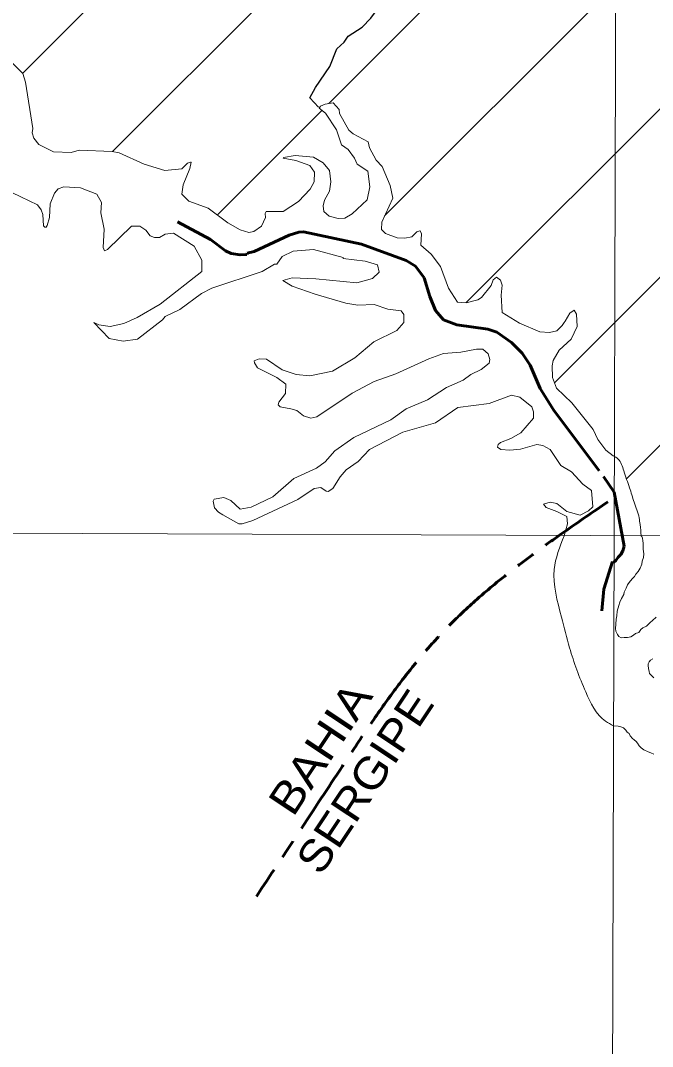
# Model space of a CAD drawing. Extents: x 553962 to 842807, y 8883888 to 9032388.
# Drawn here: x 602280 to 610250, y 8943266 to 8956198 of the extents above; entities that cross this region are included whole.
import ezdxf
from ezdxf.enums import TextEntityAlignment as Align

# ---------------------------------------------------------------- set-up
doc = ezdxf.new("R2010")
doc.units = 0
doc.header["$LTSCALE"] = 160
doc.linetypes.add('LONG_DASH_SHORT_DASH', pattern=[9.9, 6, -1.2, 1.5, -1.2])
for name, color, linetype, lineweight in [('2', 7, 'Continuous', 13), ('21', 7, 'Continuous', 25), ('30', 7, 'Continuous', 13), ('34', 7, 'LONG_DASH_SHORT_DASH', 60)]:
    doc.layers.add(name, color=color, linetype=linetype, lineweight=lineweight)

msp = doc.modelspace()

# ---------------------------------------------------------------- linework, layer by layer
at = {"layer": '2'}
msp.add_line((565315.3, 8949866.8), (791497.7, 8949052.2), dxfattribs=at)
msp.add_lwpolyline([(609971.9, 9023551.8), (609764.7, 8949706.7), (609702.8, 8928779.6)], dxfattribs=at)
at = {"layer": '21'}
msp.add_lwpolyline([(606039.3, 8955103.8), (605929.6, 8955224.5), (605999.4, 8955353.7), (606180, 8955619.3), (606269.2, 8955840.2), (606360.2, 8955926.9), (606411.5, 8955999.5), (606589.9, 8956112.1), (606699.8, 8956226.1), (606821.6, 8956390.6), (606950.7, 8956641.4)], dxfattribs=at)
at = {"layer": '21', "lineweight": 13}
for points in [[(604895.8, 8953649.4), (604648, 8953830.8), (604402.7, 8953921.2), (604313.5, 8954010.1), (604331.8, 8954124.8), (604416, 8954332.4), (604432.7, 8954411.5), (604424.9, 8954413.6), (604386.7, 8954398.7), (604315.2, 8954330), (604098.3, 8954307.6), (603837.5, 8954388.2), (603522.6, 8954529.5), (603434.3, 8954545.5), (603019.3, 8954562.1), (602920.8, 8954535.9), (602695.5, 8954541), (602512.3, 8954636.9), (602447.2, 8954715.8), (602427.7, 8954781.3), (602434.1, 8954838.6), (602343.7, 8955420.5), (602307.6, 8955528.7), (602034.6, 8955801.4)], [(609755.4, 8950712.2), (609661.1, 8950783.5), (609561, 8950917.9), (609502.2, 8951042.1), (609232.8, 8951376.9), (609037.8, 8951563.3), (608987.2, 8951699.7), (608983.5, 8951846.5), (608997.5, 8951911.8), (609071.5, 8952043.1), (609222.8, 8952181.3), (609297.8, 8952340.2), (609292, 8952494.6), (609262.3, 8952545.1), (609208.4, 8952508.9), (609150.1, 8952407.8), (609137, 8952393.4), (609112.2, 8952354.9), (609043.5, 8952286.2), (608950.9, 8952265), (608829.5, 8952275.2), (608570.6, 8952384.4), (608354.7, 8952517.4), (608341.8, 8952734.8), (608352.3, 8952862.7), (608331.7, 8952926.3), (608281.3, 8952961.5), (608241.6, 8952927.5), (608214.1, 8952858.4), (608092.3, 8952708.4), (608046.9, 8952676.2), (607900.7, 8952638.1), (607791.6, 8952649), (607678.7, 8952823.7), (607576.2, 8953096.8), (607460.3, 8953252.1), (607330.5, 8953367), (607335.3, 8953510.5), (607319.8, 8953546.9), (607315.4, 8953548.9), (607278.7, 8953534.6), (607216.5, 8953473.1), (607127, 8953454.3), (607030.5, 8953457.3), (606882.1, 8953514.2), (606832.1, 8953564.1), (606835, 8953655.9), (606976.1, 8953957.7), (606939.6, 8954118.5), (606839.8, 8954356.2), (606764, 8954436.8), (606681.6, 8954591.6), (606663.8, 8954666.8), (606474.6, 8954769), (606419, 8954817.7), (606301.8, 8955025.5), (606297.6, 8955076.7), (606224.7, 8955160), (606120.8, 8955143.2), (606065.2, 8955120.1), (606045.1, 8955091.1), (606126.8, 8955027.9), (606264.5, 8954818.1), (606327.6, 8954629.3), (606412.6, 8954571)], [(606412.6, 8954571), (606492.4, 8954462.3), (606527.5, 8954387.4), (606659.3, 8954296.9), (606686, 8954102.5), (606651.8, 8953936.7), (606463.9, 8953759.9), (606370.3, 8953707.3), (606285.1, 8953700.2), (606172.6, 8953730.1), (606105.6, 8953789.7), (606098, 8953860.6), (606114.5, 8953932), (606175.8, 8954045.5), (606193.7, 8954164.2), (606175.7, 8954305.4), (606098.8, 8954404.1), (605973.2, 8954477.1), (605744.8, 8954495.8), (605598.2, 8954469.8), (605590.6, 8954462.3), (605753.2, 8954432.8), (605930.1, 8954372.2), (605986.4, 8954284.2), (605983.7, 8954165.7), (605933.2, 8954074.1), (605787.4, 8953917.3), (605593.6, 8953791), (605376.4, 8953790.1), (605366.2, 8953765.9), (605368.2, 8953714.1), (605319.2, 8953604.5), (605221.1, 8953536.7), (605160.9, 8953526.6), (605051.4, 8953560.8), (604895.8, 8953649.4)], [(602178.8, 8954026.5), (602495.4, 8953875), (602540.8, 8953812.8), (602559.9, 8953751), (602571, 8953609), (602585, 8953593.4), (602602.1, 8953591.9), (602614.5, 8953612.1), (602644, 8953712.8), (602654.8, 8953889.2), (602707.2, 8954022.7), (602755.2, 8954075.4), (602826.2, 8954100.6), (603037.5, 8954088.3), (603242.6, 8954010), (603302.4, 8953902.3), (603291.6, 8953774.8), (603334.3, 8953568.7), (603320.8, 8953334.8), (603337.9, 8953292.8), (603376.7, 8953311.5), (603681.8, 8953605.2), (603783.3, 8953607.1), (603860.4, 8953553.3), (603916.9, 8953484.5), (603968.4, 8953462.4), (604033.7, 8953462.8), (604105.8, 8953505.2), (604208, 8953515.8), (604469.3, 8953354.2), (604566.2, 8953179.1), (604565.7, 8953033.2)], [(604565.7, 8953033.2), (604039.8, 8952623.7), (603751, 8952453.4), (603581, 8952379.4), (603408.9, 8952341.9), (603268.4, 8952362.5), (603203, 8952391.3), (603399.1, 8952188.3), (603575.4, 8952157.8), (603757.4, 8952182.5), (604071.5, 8952424.1), (604106.4, 8952466.2), (604288.1, 8952555.8), (604561.1, 8952755.6), (604691.9, 8952825.4), (605325.8, 8953035.4), (605484, 8953128.6), (605511, 8953128.4), (605579.5, 8953221.7), (605719.6, 8953290.4), (605976.2, 8953310), (606348.4, 8953209.8), (606349.1, 8953199.3), (606627.5, 8953166), (606782.2, 8953118.9), (606803.1, 8953027.3), (606720.6, 8952947.4), (606519.6, 8952891.6), (606003.2, 8952941.1)], [(606003.2, 8952941.1), (605703.8, 8952954.5), (605588.1, 8952922.2), (605703.8, 8952849.4), (605995.3, 8952749.3), (606381.6, 8952634.1), (606534.5, 8952611), (606739.1, 8952617.5), (606911.6, 8952561.5), (607081, 8952539.2), (607113.4, 8952492.8), (607113.5, 8952391.1), (607023.8, 8952292), (606734.5, 8952146.5), (606495.7, 8951946), (606213.2, 8951778.7), (605929, 8951719.6), (605757, 8951735), (605578.7, 8951796.6), (605382.1, 8951930.4), (605288.8, 8951932.5), (605226.8, 8951908.2), (605232.2, 8951881.3), (605267.2, 8951822), (605514.5, 8951699.4), (605627.5, 8951614.5), (605620, 8951495.8), (605536.3, 8951386.5), (605528.7, 8951351.7), (605555.2, 8951329.8), (605690.4, 8951305.3), (605763.9, 8951283), (605848.8, 8951216.1), (605942.1, 8951185.6), (606018, 8951204.4), (606463.2, 8951500.4), (606738.6, 8951647.1), (607011.1, 8951745.5), (607430.1, 8951933.6), (607613.6, 8951999.1), (607833.1, 8952016.1), (608030.1, 8952056.4), (608109.9, 8952056.6), (608176.9, 8951998), (608199.3, 8951925.6), (608189.8, 8951877.6), (608090.2, 8951799.8), (607960.9, 8951735.6), (607862.5, 8951666.2), (607653, 8951570.5), (607410.8, 8951418.3), (607144.4, 8951302.6), (606950.8, 8951166.6), (606482.1, 8950942.3), (606242.9, 8950775.2), (606123, 8950635.5), (606012.1, 8950556.7), (605725, 8950424.5), (605463.8, 8950193.5), (605190.6, 8950065.5), (605051.5, 8950037.1), (604931.9, 8950147.3), (604842.4, 8950186), (604720.3, 8950162.6), (604710.1, 8950138.4)], [(604710.1, 8950138.4), (604726.6, 8950056.6), (604775, 8950000.1), (604833.2, 8949967.4), (605034.8, 8949852), (605074.3, 8949852.1), (605210.6, 8949895.6), (605776.5, 8950159.4), (605984.7, 8950300.3), (606066, 8950310.7), (606133.6, 8950266.2), (606157.8, 8950260.8), (606219.7, 8950297.6), (606309.2, 8950444.5), (606386.8, 8950535.4), (606539, 8950640.6), (606679, 8950789), (607103.1, 8951009.8), (607511.4, 8951127.6), (607793.4, 8951318.1), (608189.8, 8951370), (608470.1, 8951476.1), (608576.2, 8951452.3), (608726.2, 8951326.4), (608749.8, 8951266.5), (608747.2, 8951186.9), (608590.8, 8950999.1), (608464.4, 8950928.1), (608333.9, 8950879.5), (608305.4, 8950852.7), (608293.4, 8950819), (608336.8, 8950788.8), (608450, 8950780.2), (608584.4, 8950796.9), (608792.8, 8950853.3), (608865.7, 8950839.8)], [(608865.7, 8950839.8), (608961.3, 8950792.2), (609092.6, 8950589), (609228.6, 8950508.5), (609370.6, 8950354.8), (609479, 8950274.1), (609498.7, 8950068.9), (609441.2, 8950017.2), (609336.6, 8949965), (609169.4, 8950008.4), (609042.6, 8950111.6), (608957.7, 8950128.6), (608874.2, 8950101.3), (608908.7, 8950059.5), (609044.9, 8950008.9), (609169.7, 8949947.6), (609179.8, 8949852.8), (609137, 8949702.7)], [(609792.6, 8948650.3), (609799.1, 8948692.7), (609802.3, 8948751.2), (609825.2, 8948822.9), (609838.2, 8948868.4), (609861, 8948914), (609887.1, 8948962.8), (609893.6, 8948992.1), (609916.4, 8949044.2), (609935.9, 8949083.3), (609968.5, 8949132.1), (610001.1, 8949167.9), (610023.9, 8949190.7), (610040.2, 8949220), (610069.5, 8949252.6), (610095.5, 8949294.9), (610115.1, 8949347), (610121.6, 8949382.8), (610134.6, 8949428.4), (610141.1, 8949473.9), (610130.7, 8949532.9), (610130.9, 8949558), (610131.1, 8949578), (610131.3, 8949608.1), (610129, 8949638.1), (610124.3, 8949673.2), (610117, 8949693.3), (610108.9, 8949704.2)], [(610297.5, 8948676.4), (610248.6, 8948637.3), (610219.3, 8948611.3), (610219.3, 8948611.3), (610193.3, 8948585.2), (610173.7, 8948562.4), (610128.1, 8948542.9), (610102.1, 8948520.1), (610076, 8948484.3), (610033.6, 8948471.3), (610010.8, 8948448.5), (609975, 8948429), (609932.7, 8948422.5), (609892.2, 8948420.5), (609854.5, 8948416), (609854.5, 8948416), (609825.2, 8948432.2), (609808.9, 8948458.3), (609808.9, 8948458.3), (609789.3, 8948500.6), (609782.8, 8948533.1), (609789.3, 8948588.5), (609792.6, 8948650.3)], [(610265.2, 8947912.5), (610232.9, 8947945.2), (610213.1, 8947965.4), (610205.8, 8947990.5), (610198.6, 8948030.6), (610196.3, 8948068.1), (610196.5, 8948090.7), (610206.7, 8948113.1), (610224.4, 8948135.5), (610254.5, 8948152.9)], [(609757.5, 8947308.3), (609815.9, 8947301.8), (609850.4, 8947294.2), (609884.9, 8947280.7), (609915.6, 8947253.9), (609930.9, 8947229), (609953.9, 8947209.9), (609969.3, 8947183), (609969.3, 8947183), (609998, 8947148.6), (609998, 8947148.6), (610019.1, 8947129.4), (610043.1, 8947109), (610060.4, 8947088.9), (610082.7, 8947053.7), (610107.5, 8947031), (610141.8, 8947004.9), (610141.8, 8947004.9), (610194.6, 8946980.4), (610227.1, 8946967.6), (610266.9, 8946949.8)]]:
    msp.add_lwpolyline(points, dxfattribs=at)
for points in [[(610108.9, 8949704.2), (610092.8, 8949844.8), (610081.3, 8949930.9), (610018.2, 8950125.9), (609960.9, 8950309.5), (609886.3, 8950521.8), (609817.5, 8950670.9), (609755.4, 8950712.2)], [(609137, 8949702.7), (609010, 8949279.3), (609102.4, 8948678.5), (609204.1, 8948290.3), (609407.4, 8947735.7), (609657, 8947365.9), (609757.5, 8947308.3)]]:
    msp.add_spline(points, degree=3, dxfattribs=at)
at = {"layer": '30'}
for p, q in [((602304.7, 8955531.6), (612336.4, 8965563.2)), ((603439.1, 8954544.7), (613579.2, 8964684.7)), ((606166.4, 8955150.6), (614785.7, 8963769.9)), ((606871.9, 8953734.8), (615955.3, 8962818.2)), ((607896.9, 8952638.5), (617108.2, 8961849.8)), ((609012.2, 8951632.4), (618151, 8960771.3)), ((609922.6, 8950421.5), (619125.3, 8959624.2)), ((604762.6, 8953746.8), (606079.9, 8955064.1))]:
    msp.add_line(p, q, dxfattribs=at)
at = {"layer": '34'}
for points in [[(604260.6, 8953658.9), (604677.1, 8953437.9), (604865.4, 8953293), (604936.7, 8953262.7), (605049.2, 8953243.2), (605133.2, 8953249.7), (605140.2, 8953264.9), (605226.7, 8953286.6), (605667.4, 8953494), (605788.2, 8953530.6), (605849.3, 8953532.9), (606579.7, 8953379.4), (607141.7, 8953171.8), (607262.6, 8953100.6), (607368.8, 8952953.3), (607440, 8952718.2), (607513.5, 8952540.9), (607615, 8952426.2), (607782.6, 8952361), (608175.1, 8952307.1), (608287.5, 8952268.2), (608473.6, 8952138.4), (608607.4, 8952004.5), (608709, 8951855.3), (608834.6, 8951559), (609001.1, 8951288.7), (609632.1, 8950450.2), (609766.1, 8950251.3)], [(609766.1, 8950251.3), (609892.1, 8949571.8), (609876.7, 8949511.8), (609848.8, 8949469.3), (609818.6, 8949432), (609785.7, 8949389.6), (609763.6, 8949371.8)], [(609608.9, 8948758.3), (609638.2, 8949029.6), (609745.9, 8949377.2)]]:
    msp.add_lwpolyline(points, dxfattribs=at)
msp.add_spline([(609688.1, 8950131.7), (607584.3, 8948466.4), (606301.7, 8946741.8), (605255.1, 8945156.9)], degree=3, dxfattribs=at)

# ---------------------------------------------------------------- texts
for s, width, p in [('BAHIA', 1.15, (606226.5, 8946914.2)), ('SERGIPE', 1.1, (606788.4, 8946494.9))]:
    msp.add_text(s, height=400, rotation=56.48, dxfattribs=dict(at, width=width)).set_placement(p, align=Align.CENTER)

doc.saveas('drawing.dxf')
